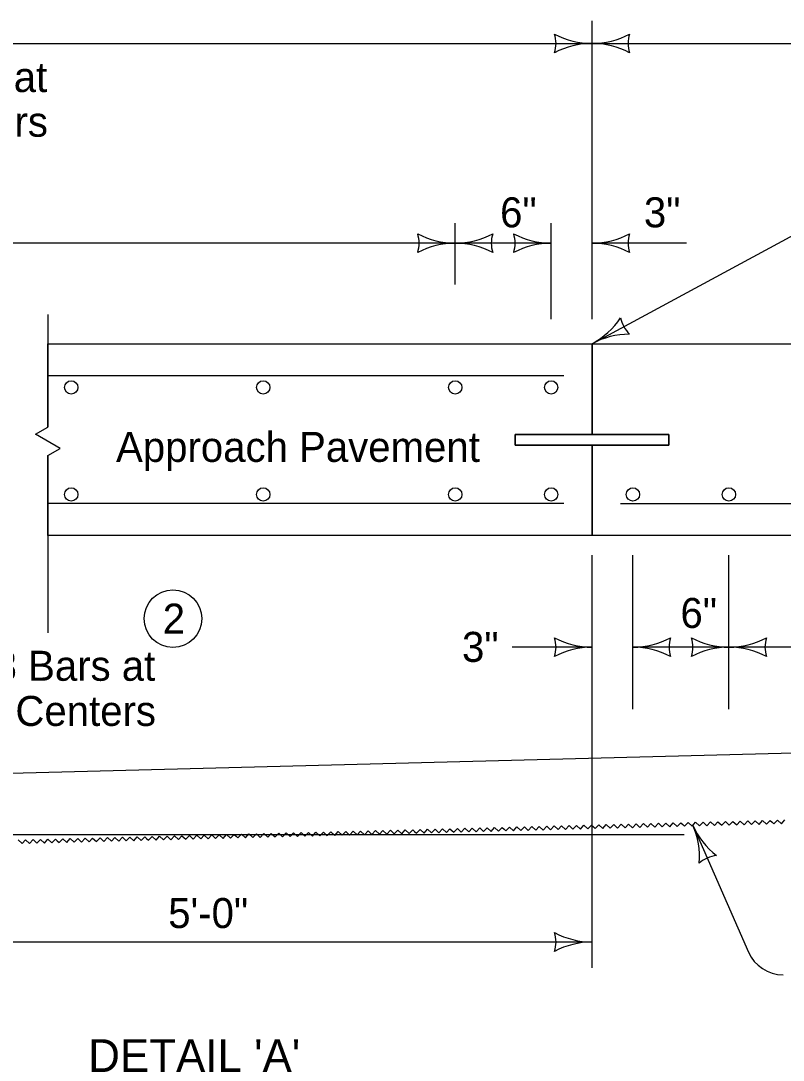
# Model space of a CAD drawing. Extents: x -2135039 to -2124495, y -2139046 to -2132546.
# Drawn here: x -2133420 to -2133014, y -2134286 to -2133732 of the extents above; entities that cross this region are included whole.
import ezdxf

# ---------------------------------------------------------------- set-up
doc = ezdxf.new("R2010")
doc.units = 0
for name, color, linetype in [('BridgeSuperStructureExisting', 7, 'Continuous'), ('dsnCellElements', 7, 'Continuous'), ('dsnStdLabel', 7, 'Continuous'), ('dsnTextFinalPlan', 7, 'Continuous')]:
    doc.layers.add(name, color=color, linetype=linetype)

msp = doc.modelspace()

# ---------------------------------------------------------------- linework, layer by layer
at = {"layer": 'BridgeSuperStructureExisting'}
for p, q in [((-2133406.02, -2133888.19), (-2133406.02, -2133948.27)), ((-2133116, -2133952.14), (-2133116, -2133903.82)), ((-2133116, -2133952.14), (-2133116, -2133903.82)), ((-2133131.07, -2133920.87), (-2133406.02, -2133920.87)), ((-2133156.92, -2133957.82), (-2133156.92, -2133952.14)), ((-2133156.92, -2133952.14), (-2133075.08, -2133952.14)), ((-2133156.92, -2133957.82), (-2133156.92, -2133952.14)), ((-2133156.92, -2133952.14), (-2133075.08, -2133952.14)), ((-2133075.08, -2133952.14), (-2133075.08, -2133957.82)), ((-2133075.08, -2133952.14), (-2133075.08, -2133957.82)), ((-2133075.08, -2133957.82), (-2133156.92, -2133957.82)), ((-2133075.08, -2133957.82), (-2133156.92, -2133957.82)), ((-2133116, -2134006.13), (-2133116, -2133957.82)), ((-2133116, -2134006.13), (-2133116, -2133957.82)), ((-2133406.02, -2133963.43), (-2133406.02, -2134058.04)), ((-2133131.07, -2133989.08), (-2133406.02, -2133989.08)), ((-2133131.07, -2133989.08), (-2133406.02, -2133989.08)), ((-2133100.93, -2133989.08), (-2132639.61, -2133989.08)), ((-2133100.93, -2133989.08), (-2132639.61, -2133989.08)), ((-2133457.76, -2134165.59), (-2133066.86, -2134165.59))]:
    msp.add_line(p, q, dxfattribs=at)
msp.add_lwpolyline([(-2133406.02, -2133963.42), (-2133399.45, -2133959.64), (-2133412.59, -2133952.05), (-2133406.02, -2133948.26)], dxfattribs=at)
msp.add_lwpolyline([(-2133406.02, -2133963.42), (-2133399.45, -2133959.64), (-2133412.59, -2133952.05), (-2133406.02, -2133948.26)], dxfattribs=at)
msp.add_circle((-2133339.37, -2134050.42), 15.36, dxfattribs=at)
at = {"layer": 'dsnCellElements'}
for centre, radius, start, end in [((-2133151.64, -2133743.62), 16.42, 342.2666, 17.7333), ((-2133116, -2133701.12), 42.5, 241.9275, 270), ((-2133116, -2133701.12), 42.5, 270, 298.0725), ((-2133080.37, -2133743.62), 16.42, 162.2666, 197.7334), ((-2133116, -2133786.12), 42.5, 90, 118.0725), ((-2133116, -2133786.12), 42.5, 61.9275, 90), ((-2133224.57, -2133850.18), 16.42, 342.2666, 17.7333), ((-2133188.94, -2133807.68), 42.5, 241.9275, 270), ((-2133188.94, -2133807.68), 42.5, 270, 298.0725), ((-2133153.3, -2133850.18), 16.42, 162.2666, 197.7334), ((-2133173.42, -2133850.18), 16.42, 342.2666, 17.7333), ((-2133137.79, -2133807.68), 42.5, 241.9275, 270), ((-2133116, -2133807.68), 42.5, 270, 298.0725), ((-2133080.37, -2133850.18), 16.42, 162.2666, 197.7334), ((-2133188.94, -2133892.68), 42.5, 90, 118.0725), ((-2133188.94, -2133892.68), 42.5, 61.9275, 90), ((-2133137.79, -2133892.68), 42.5, 90, 118.0725), ((-2133116, -2133892.68), 42.5, 61.9275, 90), ((-2133136.23, -2133866.45), 42.5, 298.4258, 326.4983), ((-2133084.66, -2133886.86), 16.42, 190.6925, 226.1592), ((-2133095.77, -2133941.2), 42.5, 90.3533, 118.4258), ((-2133151.64, -2134065.63), 16.42, 342.2666, 17.7333), ((-2133116, -2134023.13), 42.5, 241.9275, 270), ((-2133116, -2134108.13), 42.5, 90, 118.0725), ((-2133094.22, -2134023.13), 42.5, 270, 298.0725), ((-2133094.22, -2134108.13), 42.5, 61.9275, 90), ((-2133058.58, -2134065.63), 16.42, 162.2666, 197.7334), ((-2133078.7, -2134065.63), 16.42, 342.2666, 17.7333), ((-2133043.07, -2134023.13), 42.5, 241.9275, 270), ((-2133043.07, -2134108.13), 42.5, 90, 118.0725), ((-2133043.07, -2134023.13), 42.5, 270, 298.0725), ((-2133043.07, -2134108.13), 42.5, 61.9275, 90), ((-2133007.43, -2134065.63), 16.42, 162.2666, 197.7334), ((-2133023.38, -2134143.46), 42.5, 203.6401, 231.7126), ((-2133101.25, -2134177.54), 42.5, 355.5676, 23.6401), ((-2133048.02, -2134193.14), 16.42, 95.9068, 131.3735), ((-2133151.64, -2134222.88), 16.42, 342.2666, 17.7333), ((-2133116, -2134180.38), 42.5, 241.9275, 270), ((-2133116, -2134265.38), 42.5, 90, 118.0725)]:
    msp.add_arc(centre, radius, start, end, dxfattribs=at)
at = {"layer": 'dsnStdLabel'}
for p, q in [((-2133116, -2133890.78), (-2133116, -2133731.57)), ((-2134488.25, -2133743.62), (-2133116, -2133743.62)), ((-2133116, -2133743.62), (-2132147.37, -2133743.62)), ((-2133116, -2133903.82), (-2132952.81, -2133815.49)), ((-2133188.94, -2133872.16), (-2133188.94, -2133839.59)), ((-2133137.79, -2133890.78), (-2133137.79, -2133839.59)), ((-2133188.94, -2133850.18), (-2133814.91, -2133850.18)), ((-2133137.79, -2133850.18), (-2133188.94, -2133850.18)), ((-2133065.6, -2133850.18), (-2133116, -2133850.18)), ((-2133406.02, -2133948.27), (-2133406.02, -2133903.82)), ((-2133406.02, -2133903.82), (-2133116, -2133903.82)), ((-2133406.02, -2133903.82), (-2133116, -2133903.82)), ((-2133116, -2133903.82), (-2133116, -2133952.14)), ((-2133116, -2133952.14), (-2133116, -2133903.82)), ((-2133116, -2133903.82), (-2132639.61, -2133903.82)), ((-2133116, -2133952.14), (-2133116, -2133903.82)), ((-2133116, -2133903.82), (-2132639.61, -2133903.82)), ((-2133116, -2133952.14), (-2133116, -2133903.82)), ((-2133406.02, -2133948.26), (-2133406.02, -2133948.27)), ((-2133116, -2133952.14), (-2133156.92, -2133952.13)), ((-2133156.92, -2133952.13), (-2133156.92, -2133957.82)), ((-2133156.92, -2133952.13), (-2133156.92, -2133957.82)), ((-2133156.92, -2133952.14), (-2133156.92, -2133957.82)), ((-2133075.08, -2133952.13), (-2133116, -2133952.14)), ((-2133075.08, -2133957.82), (-2133075.08, -2133952.13)), ((-2133075.08, -2133957.82), (-2133075.08, -2133952.13)), ((-2133075.08, -2133957.82), (-2133075.08, -2133952.14)), ((-2133156.92, -2133957.82), (-2133116, -2133957.82)), ((-2133075.08, -2133957.82), (-2133156.92, -2133957.82)), ((-2133116, -2133957.82), (-2133116, -2134006.13)), ((-2133116, -2134006.13), (-2133116, -2133957.82)), ((-2133116, -2133957.82), (-2133075.08, -2133957.82)), ((-2133116, -2134006.13), (-2133116, -2133957.82)), ((-2133116, -2134006.13), (-2133116, -2133957.82)), ((-2133406.02, -2134006.13), (-2133406.02, -2133963.43)), ((-2133116, -2134006.13), (-2133406.02, -2134006.13)), ((-2133116, -2134006.13), (-2133406.02, -2134006.13)), ((-2132639.61, -2134006.13), (-2133116, -2134006.13)), ((-2132639.61, -2134006.13), (-2133116, -2134006.13)), ((-2133116, -2134236.65), (-2133116, -2134016.62)), ((-2133094.22, -2134098.63), (-2133094.22, -2134016.62)), ((-2133043.07, -2134098.63), (-2133043.07, -2134016.62)), ((-2133116, -2134065.63), (-2133158.63, -2134065.63)), ((-2133043.07, -2134065.63), (-2133094.22, -2134065.63)), ((-2132220.31, -2134065.63), (-2133043.07, -2134065.63)), ((-2133734.23, -2134140.93), (-2132639.24, -2134112.34)), ((-2133062.31, -2134160.5), (-2133032.66, -2134228.25)), ((-2133116, -2134222.88), (-2133525.22, -2134222.88))]:
    msp.add_line(p, q, dxfattribs=at)
for points in [[(-2133406.02, -2133963.42), (-2133399.45, -2133959.64), (-2133412.59, -2133952.05), (-2133406.02, -2133948.26)], [(-2133115.32, -2134161.45), (-2133114.31, -2134162.42), (-2133112.38, -2134160.38), (-2133110.34, -2134162.31), (-2133108.41, -2134160.28), (-2133106.37, -2134162.21), (-2133104.44, -2134160.17), (-2133102.4, -2134162.1), (-2133100.47, -2134160.07), (-2133098.43, -2134162), (-2133096.5, -2134159.97), (-2133094.47, -2134161.9), (-2133092.54, -2134159.86), (-2133090.5, -2134161.79), (-2133088.57, -2134159.76), (-2133086.53, -2134161.69), (-2133084.6, -2134159.66), (-2133082.56, -2134161.59), (-2133080.63, -2134159.55), (-2133078.59, -2134161.48), (-2133076.66, -2134159.45), (-2133074.63, -2134161.38), (-2133072.7, -2134159.35), (-2133070.66, -2134161.28), (-2133068.73, -2134159.24), (-2133067.71, -2134160.2)], [(-2133067.71, -2134160.2), (-2133066.7, -2134161.17), (-2133064.76, -2134159.14), (-2133062.73, -2134161.07), (-2133060.8, -2134159.03), (-2133058.76, -2134160.96), (-2133056.83, -2134158.93), (-2133054.8, -2134160.86), (-2133052.86, -2134158.83), (-2133050.83, -2134160.76), (-2133048.89, -2134158.73), (-2133046.86, -2134160.65), (-2133044.93, -2134158.62), (-2133042.89, -2134160.55), (-2133040.96, -2134158.52), (-2133038.92, -2134160.45), (-2133036.99, -2134158.42), (-2133034.96, -2134160.34), (-2133033.02, -2134158.31), (-2133030.99, -2134160.24), (-2133029.06, -2134158.21), (-2133027.02, -2134160.14), (-2133025.09, -2134158.1), (-2133023.05, -2134160.04), (-2133021.12, -2134158), (-2133020.1, -2134158.97)], [(-2133020.1, -2134158.97), (-2133019.09, -2134159.93), (-2133017.16, -2134157.89), (-2133015.12, -2134159.83), (-2133013.19, -2134157.79)], [(-2133353.36, -2134167.67), (-2133352.35, -2134168.63), (-2133350.41, -2134166.6), (-2133348.38, -2134168.53), (-2133346.45, -2134166.49), (-2133344.41, -2134168.43), (-2133342.48, -2134166.39), (-2133340.44, -2134168.32), (-2133338.51, -2134166.28), (-2133336.48, -2134168.22), (-2133334.55, -2134166.19), (-2133332.51, -2134168.11), (-2133330.58, -2134166.08), (-2133328.54, -2134168.01), (-2133326.61, -2134165.98), (-2133324.57, -2134167.91), (-2133322.64, -2134165.87), (-2133320.61, -2134167.8), (-2133318.67, -2134165.77), (-2133316.64, -2134167.7), (-2133314.71, -2134165.67), (-2133312.67, -2134167.59), (-2133310.74, -2134165.57), (-2133308.7, -2134167.49), (-2133306.77, -2134165.46), (-2133305.75, -2134166.43)], [(-2133305.75, -2134166.43), (-2133304.74, -2134167.39), (-2133302.8, -2134165.35), (-2133300.77, -2134167.29), (-2133298.84, -2134165.25), (-2133296.8, -2134167.18), (-2133294.87, -2134165.15), (-2133292.84, -2134167.08), (-2133290.9, -2134165.05), (-2133288.87, -2134166.97), (-2133286.93, -2134164.94), (-2133284.9, -2134166.87), (-2133282.97, -2134164.84), (-2133280.93, -2134166.77), (-2133279, -2134164.73), (-2133276.96, -2134166.66), (-2133275.03, -2134164.63), (-2133273, -2134166.56), (-2133271.07, -2134164.53), (-2133269.03, -2134166.45), (-2133267.1, -2134164.42), (-2133265.06, -2134166.35), (-2133263.13, -2134164.32), (-2133261.09, -2134166.25), (-2133259.16, -2134164.21), (-2133258.15, -2134165.18)], [(-2133258.15, -2134165.18), (-2133257.13, -2134166.15), (-2133255.2, -2134164.11), (-2133253.16, -2134166.04), (-2133251.23, -2134164.01), (-2133249.2, -2134165.94), (-2133247.26, -2134163.9), (-2133245.23, -2134165.83), (-2133243.29, -2134163.8), (-2133241.26, -2134165.73), (-2133239.32, -2134163.7), (-2133237.29, -2134165.63), (-2133235.36, -2134163.59), (-2133233.33, -2134165.52), (-2133231.39, -2134163.49), (-2133229.36, -2134165.42), (-2133227.43, -2134163.39), (-2133225.39, -2134165.31), (-2133223.46, -2134163.28), (-2133221.42, -2134165.21), (-2133219.49, -2134163.18), (-2133217.46, -2134165.11), (-2133215.52, -2134163.07), (-2133213.49, -2134165.01), (-2133211.55, -2134162.97), (-2133210.54, -2134163.94)], [(-2133210.54, -2134163.94), (-2133209.52, -2134164.9), (-2133207.59, -2134162.87), (-2133205.55, -2134164.8), (-2133203.62, -2134162.76), (-2133201.58, -2134164.7), (-2133199.66, -2134162.66), (-2133197.62, -2134164.59), (-2133195.69, -2134162.56), (-2133193.65, -2134164.49), (-2133191.72, -2134162.45), (-2133189.68, -2134164.38), (-2133187.75, -2134162.35), (-2133185.72, -2134164.28), (-2133183.78, -2134162.25), (-2133181.75, -2134164.17), (-2133179.81, -2134162.14), (-2133177.79, -2134164.07), (-2133175.85, -2134162.04), (-2133173.81, -2134163.97), (-2133171.88, -2134161.94), (-2133169.85, -2134163.87), (-2133167.92, -2134161.83), (-2133165.88, -2134163.76), (-2133163.95, -2134161.73), (-2133162.93, -2134162.69)], [(-2133162.93, -2134162.69), (-2133161.91, -2134163.66), (-2133159.98, -2134161.62), (-2133157.94, -2134163.56), (-2133156.01, -2134161.52), (-2133153.98, -2134163.45), (-2133152.05, -2134161.42), (-2133150.01, -2134163.35), (-2133148.08, -2134161.31), (-2133146.04, -2134163.24), (-2133144.11, -2134161.21), (-2133142.08, -2134163.14), (-2133140.15, -2134161.11), (-2133138.1, -2134163.03), (-2133136.17, -2134161), (-2133134.14, -2134162.93), (-2133132.21, -2134160.9), (-2133130.18, -2134162.83), (-2133128.24, -2134160.8), (-2133126.21, -2134162.73), (-2133124.27, -2134160.69), (-2133122.24, -2134162.62), (-2133120.31, -2134160.59), (-2133118.27, -2134162.52), (-2133116.34, -2134160.49), (-2133115.32, -2134161.45)], [(-2133421.82, -2134168.47), (-2133419.78, -2134170.39), (-2133417.86, -2134168.36), (-2133415.82, -2134170.29), (-2133413.89, -2134168.26), (-2133411.85, -2134170.19), (-2133409.92, -2134168.15), (-2133407.89, -2134170.08), (-2133405.95, -2134168.05), (-2133403.92, -2134169.98), (-2133401.99, -2134167.95), (-2133400.97, -2134168.91)], [(-2133400.97, -2134168.91), (-2133399.96, -2134169.87), (-2133398.02, -2134167.84), (-2133395.99, -2134169.77), (-2133394.06, -2134167.74), (-2133392.02, -2134169.67), (-2133390.09, -2134167.63), (-2133388.05, -2134169.57), (-2133386.12, -2134167.53), (-2133384.08, -2134169.46), (-2133382.15, -2134167.42), (-2133380.12, -2134169.36), (-2133378.18, -2134167.33), (-2133376.15, -2134169.25), (-2133374.22, -2134167.22), (-2133372.18, -2134169.15), (-2133370.25, -2134167.12), (-2133368.21, -2134169.05), (-2133366.28, -2134167.01), (-2133364.24, -2134168.94), (-2133362.31, -2134166.91), (-2133360.28, -2134168.84), (-2133358.35, -2134166.81), (-2133356.31, -2134168.73), (-2133354.38, -2134166.7), (-2133353.36, -2134167.67)]]:
    msp.add_lwpolyline(points, dxfattribs=at)
msp.add_arc((-2133014.14, -2134220.14), 20.21, 203.6401, 270, dxfattribs=at)
at = {"layer": 'dsnTextFinalPlan'}
for centre in [(-2133393.55, -2133927.08), (-2133393.55, -2133927.08), (-2133291.24, -2133927.08), (-2133188.94, -2133927.08), (-2133137.79, -2133927.08), (-2133393.55, -2133984.18), (-2133291.24, -2133984.18), (-2133188.94, -2133984.18), (-2133137.79, -2133984.18), (-2133094.22, -2133984.18), (-2133043.07, -2133984.18)]:
    msp.add_circle(centre, 3.55, dxfattribs=at)

# ---------------------------------------------------------------- texts
at = {"layer": 'BridgeSuperStructureExisting'}
msp.add_text("DETAIL 'A' ", height=17.5, dxfattribs=at).set_placement((-2133384.51, -2134292.2))
at = {"layer": 'dsnStdLabel'}
for s, p in [('#5 Bars at', (-2133503.87, -2133769.58)), ('12" Centers', (-2133518.23, -2133793.41)), ('6"', (-2133165.02, -2133841.72)), ('3"', (-2133088.38, -2133841.72)), ('Approach Pavement', (-2133369.68, -2133966.83)), ('2', (-2133344.81, -2134058.42)), ('6"', (-2133068.9, -2134055.38)), ('3"', (-2133185.31, -2134073.48)), ('#8 Bars at', (-2133446.29, -2134083.55)), ('12" Centers', (-2133460.65, -2134107.64)), ('5\'-0"', (-2133341.87, -2134215.43))]:
    msp.add_text(s, height=16, dxfattribs=at).set_placement(p)

doc.saveas('drawing.dxf')
